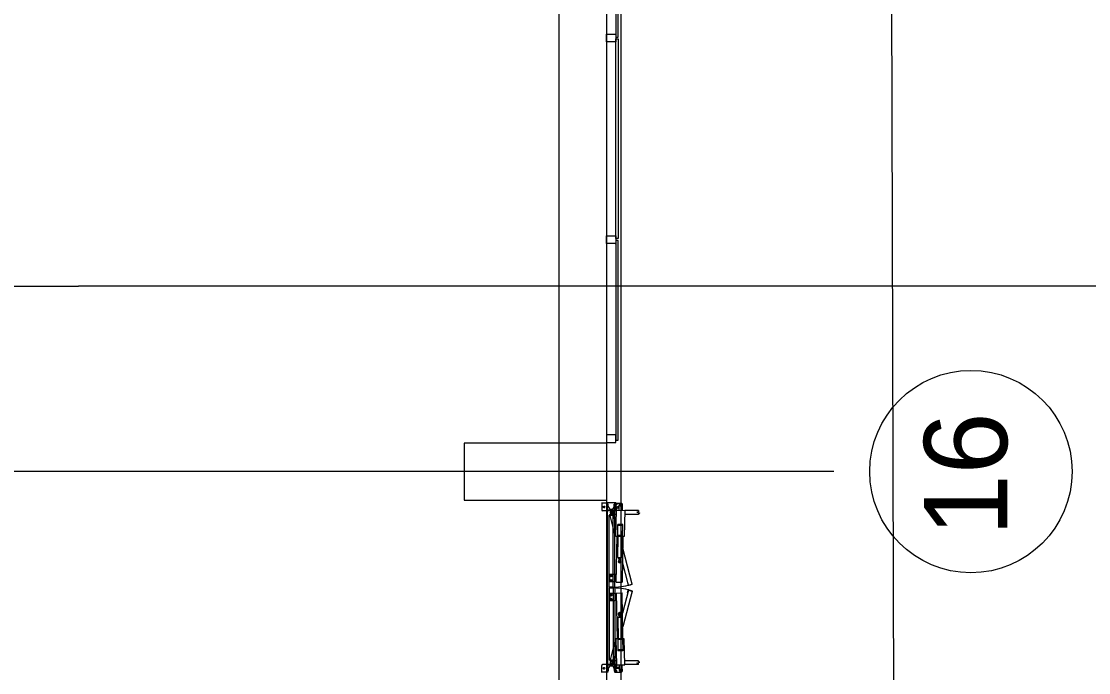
# Model space of a CAD drawing. Extents: x -264031 to -263588, y -1242281 to -1242059.
# Drawn here: x -263801.2 to -263789.97, y -1242184 to -1242177.15 of the extents above; entities that cross this region are included whole.
import ezdxf

# ---------------------------------------------------------------- set-up
doc = ezdxf.new("R2010")
doc.units = 0
for name, color, linetype in [('HESCON_OSI_STAVBY_KFA', 7, 'Continuous'), ('KFA_2D_SITUACIA_DSP', 7, 'Continuous'), ('KFA_JESTV_IS_DSP_-_KANAL_SPLASK', 7, 'Continuous')]:
    doc.layers.add(name, color=color, linetype=linetype)

msp = doc.modelspace()

# ---------------------------------------------------------------- linework, layer by layer
at = {"layer": 'HESCON_OSI_STAVBY_KFA'}
for p, q in [((-263795.543, -1242083.237), (-263795.543, -1242246.707)), ((-263792.653, -1242181.882), (-263909.343, -1242181.882)), ((-263792.653, -1242181.882), (-263792.653, -1242181.882))]:
    msp.add_line(p, q, dxfattribs=at)
msp.add_circle((-263791.21, -1242181.882), 1.064, dxfattribs=at)
at = {"layer": 'KFA_2D_SITUACIA_DSP'}
for p, q in [((-263795.043, -1242101.769), (-263795.043, -1242226.995)), ((-263794.943, -1242175.212), (-263794.943, -1242177.312)), ((-263794.918, -1242177.312), (-263794.918, -1242175.212)), ((-263795.043, -1242177.362), (-263795.043, -1242177.282)), ((-263795.043, -1242177.282), (-263794.943, -1242177.282)), ((-263794.943, -1242177.362), (-263795.043, -1242177.362)), ((-263794.943, -1242177.282), (-263794.943, -1242177.322)), ((-263794.943, -1242177.312), (-263794.918, -1242177.312)), ((-263794.943, -1242177.322), (-263794.943, -1242177.362)), ((-263794.943, -1242179.432), (-263794.943, -1242177.332)), ((-263794.943, -1242177.332), (-263794.918, -1242177.332)), ((-263794.918, -1242177.332), (-263794.918, -1242179.432)), ((-263795.043, -1242179.482), (-263795.043, -1242179.402)), ((-263795.043, -1242179.402), (-263794.943, -1242179.402)), ((-263794.943, -1242179.482), (-263795.043, -1242179.482)), ((-263794.943, -1242179.402), (-263794.943, -1242179.492)), ((-263794.918, -1242179.432), (-263794.943, -1242179.432)), ((-263794.918, -1242179.452), (-263794.943, -1242179.452)), ((-263794.943, -1242179.452), (-263794.943, -1242181.552)), ((-263794.943, -1242179.492), (-263794.943, -1242179.482)), ((-263794.918, -1242181.552), (-263794.918, -1242179.452)), ((-263801.593, -1242179.932), (-263800.593, -1242179.932)), ((-263788.893, -1242179.932), (-263800.593, -1242179.932)), ((-263794.943, -1242181.497), (-263795.043, -1242181.497)), ((-263795.043, -1242181.497), (-263795.043, -1242181.577)), ((-263794.943, -1242181.537), (-263794.943, -1242181.497)), ((-263795.038, -1242181.582), (-263796.538, -1242181.582)), ((-263796.538, -1242181.582), (-263796.538, -1242182.182)), ((-263795.043, -1242181.577), (-263794.943, -1242181.577)), ((-263795.038, -1242182.182), (-263795.038, -1242181.582)), ((-263794.943, -1242181.577), (-263794.943, -1242181.537)), ((-263794.943, -1242181.552), (-263794.918, -1242181.552)), ((-263796.538, -1242182.182), (-263795.038, -1242182.182)), ((-263795.093, -1242182.208), (-263795.093, -1242182.284)), ((-263795.033, -1242182.214), (-263795.093, -1242182.214)), ((-263795.033, -1242182.294), (-263795.083, -1242182.294)), ((-263795.055, -1242182.254), (-263795.081, -1242182.254)), ((-263795.068, -1242182.241), (-263795.068, -1242182.267)), ((-263795.043, -1242182.208), (-263794.943, -1242182.208)), ((-263795.033, -1242183.102), (-263795.033, -1242182.208)), ((-263795.025, -1242182.224), (-263795.033, -1242182.224)), ((-263794.953, -1242182.288), (-263795.033, -1242182.288)), ((-263794.953, -1242182.294), (-263795.033, -1242182.294)), ((-263795.025, -1242182.245), (-263795.025, -1242182.224)), ((-263795.005, -1242182.288), (-263794.98, -1242182.288)), ((-263795.005, -1242182.288), (-263795.005, -1242182.298)), ((-263795.005, -1242182.298), (-263794.98, -1242182.298)), ((-263794.994, -1242182.298), (-263795.001, -1242182.308)), ((-263794.992, -1242182.298), (-263794.994, -1242182.298)), ((-263794.985, -1242182.308), (-263794.992, -1242182.298)), ((-263794.98, -1242182.288), (-263794.98, -1242182.298)), ((-263794.977, -1242182.301), (-263794.977, -1242182.326)), ((-263794.967, -1242182.301), (-263794.977, -1242182.301)), ((-263794.967, -1242182.333), (-263794.967, -1242182.293)), ((-263794.937, -1242182.293), (-263794.967, -1242182.293)), ((-263794.967, -1242182.301), (-263794.967, -1242182.326)), ((-263794.96, -1242182.245), (-263794.96, -1242182.224)), ((-263794.953, -1242182.224), (-263794.96, -1242182.224)), ((-263794.953, -1242183.102), (-263794.953, -1242182.208)), ((-263794.953, -1242182.213), (-263794.943, -1242182.213)), ((-263794.953, -1242182.213), (-263794.953, -1242182.283)), ((-263794.953, -1242182.283), (-263794.943, -1242182.283)), ((-263794.937, -1242182.294), (-263794.953, -1242182.294)), ((-263794.933, -1242182.223), (-263794.947, -1242182.223)), ((-263794.933, -1242182.272), (-263794.947, -1242182.272)), ((-263794.943, -1242182.213), (-263794.893, -1242182.213)), ((-263794.943, -1242182.213), (-263794.943, -1242182.283)), ((-263794.943, -1242182.232), (-263794.943, -1242182.215)), ((-263794.941, -1242182.215), (-263794.943, -1242182.215)), ((-263794.941, -1242182.232), (-263794.943, -1242182.232)), ((-263794.943, -1242182.253), (-263794.908, -1242182.253)), ((-263794.943, -1242182.281), (-263794.943, -1242182.264)), ((-263794.941, -1242182.264), (-263794.943, -1242182.264)), ((-263794.941, -1242182.281), (-263794.943, -1242182.281)), ((-263794.943, -1242182.564), (-263794.937, -1242182.289)), ((-263794.941, -1242182.232), (-263794.941, -1242182.215)), ((-263794.941, -1242182.23), (-263794.941, -1242182.217)), ((-263794.941, -1242182.217), (-263794.935, -1242182.217)), ((-263794.941, -1242182.223), (-263794.936, -1242182.223)), ((-263794.935, -1242182.23), (-263794.941, -1242182.23)), ((-263794.941, -1242182.281), (-263794.941, -1242182.264)), ((-263794.941, -1242182.279), (-263794.941, -1242182.266)), ((-263794.941, -1242182.266), (-263794.935, -1242182.266)), ((-263794.941, -1242182.272), (-263794.936, -1242182.272)), ((-263794.935, -1242182.279), (-263794.941, -1242182.279)), ((-263794.937, -1242182.289), (-263794.85, -1242182.29)), ((-263794.935, -1242182.217), (-263794.935, -1242182.23)), ((-263794.935, -1242182.266), (-263794.935, -1242182.279)), ((-263794.908, -1242182.254), (-263794.927, -1242182.254)), ((-263794.918, -1242182.253), (-263794.918, -1242182.264)), ((-263794.909, -1242182.289), (-263794.908, -1242182.233)), ((-263794.877, -1242182.233), (-263794.908, -1242182.233)), ((-263794.899, -1242182.223), (-263794.905, -1242182.233)), ((-263794.905, -1242182.233), (-263794.899, -1242182.244)), ((-263794.887, -1242182.223), (-263794.899, -1242182.223)), ((-263794.899, -1242182.244), (-263794.887, -1242182.244)), ((-263794.893, -1242182.218), (-263794.893, -1242182.249)), ((-263794.881, -1242182.233), (-263794.887, -1242182.223)), ((-263794.887, -1242182.244), (-263794.881, -1242182.233)), ((-263794.878, -1242182.234), (-263794.879, -1242182.29)), ((-263794.85, -1242182.29), (-263794.856, -1242182.565)), ((-263794.707, -1242182.293), (-263794.85, -1242182.293)), ((-263794.707, -1242182.293), (-263794.707, -1242182.305)), ((-263795.013, -1242183.097), (-263795.013, -1242182.339)), ((-263794.973, -1242182.339), (-263795.013, -1242182.339)), ((-263795.005, -1242182.339), (-263795.005, -1242182.329)), ((-263795.005, -1242182.329), (-263794.98, -1242182.329)), ((-263795.005, -1242182.343), (-263794.967, -1242182.333)), ((-263795.005, -1242182.339), (-263794.98, -1242182.339)), ((-263794.953, -1242182.54), (-263795.005, -1242182.343)), ((-263795.001, -1242182.319), (-263794.994, -1242182.329)), ((-263794.977, -1242182.325), (-263795.001, -1242182.332)), ((-263794.998, -1242182.341), (-263795.001, -1242182.332)), ((-263794.99, -1242182.329), (-263794.999, -1242182.321)), ((-263794.994, -1242182.329), (-263794.992, -1242182.329)), ((-263794.992, -1242182.329), (-263794.985, -1242182.319)), ((-263794.988, -1242182.328), (-263794.99, -1242182.329)), ((-263794.983, -1242182.317), (-263794.988, -1242182.328)), ((-263794.987, -1242182.305), (-263794.977, -1242182.312)), ((-263794.977, -1242182.314), (-263794.987, -1242182.322)), ((-263794.98, -1242182.339), (-263794.98, -1242182.329)), ((-263794.977, -1242182.312), (-263794.977, -1242182.314)), ((-263794.974, -1242182.335), (-263794.977, -1242182.325)), ((-263794.967, -1242182.326), (-263794.977, -1242182.326)), ((-263794.973, -1242183.097), (-263794.973, -1242182.339)), ((-263794.938, -1242182.333), (-263794.967, -1242182.333)), ((-263794.953, -1242182.386), (-263794.967, -1242182.333)), ((-263794.707, -1242182.333), (-263794.851, -1242182.333)), ((-263794.707, -1242182.305), (-263794.722, -1242182.309)), ((-263794.722, -1242182.309), (-263794.692, -1242182.318)), ((-263794.692, -1242182.318), (-263794.707, -1242182.322)), ((-263794.707, -1242182.322), (-263794.707, -1242182.333)), ((-263794.924, -1242182.564), (-263794.922, -1242182.438)), ((-263794.872, -1242182.439), (-263794.922, -1242182.438)), ((-263794.872, -1242182.449), (-263794.922, -1242182.448)), ((-263794.874, -1242182.565), (-263794.872, -1242182.439)), ((-263794.856, -1242182.565), (-263794.943, -1242182.564)), ((-263794.939, -1242183.045), (-263794.93, -1242182.564)), ((-263794.874, -1242182.555), (-263794.924, -1242182.554)), ((-263794.924, -1242182.787), (-263794.919, -1242182.564)), ((-263794.884, -1242182.788), (-263794.879, -1242182.565)), ((-263794.869, -1242182.565), (-263794.878, -1242183.046)), ((-263794.772, -1242183.066), (-263794.871, -1242182.689)), ((-263794.884, -1242182.788), (-263794.924, -1242182.787)), ((-263794.909, -1242182.808), (-263794.917, -1242182.821)), ((-263794.914, -1242182.792), (-263794.914, -1242182.787)), ((-263794.894, -1242182.792), (-263794.914, -1242182.792)), ((-263794.912, -1242182.792), (-263794.914, -1242182.793)), ((-263794.914, -1242182.799), (-263794.914, -1242182.793)), ((-263794.913, -1242182.8), (-263794.914, -1242182.799)), ((-263794.896, -1242182.8), (-263794.913, -1242182.8)), ((-263794.895, -1242182.792), (-263794.912, -1242182.792)), ((-263794.909, -1242182.799), (-263794.909, -1242182.793)), ((-263794.909, -1242182.808), (-263794.909, -1242182.8)), ((-263794.909, -1242182.808), (-263794.899, -1242182.808)), ((-263794.899, -1242182.8), (-263794.899, -1242182.793)), ((-263794.899, -1242182.808), (-263794.899, -1242182.8)), ((-263794.899, -1242182.808), (-263794.892, -1242182.822)), ((-263794.896, -1242182.8), (-263794.894, -1242182.8)), ((-263794.895, -1242182.792), (-263794.894, -1242182.793)), ((-263794.894, -1242182.792), (-263794.894, -1242182.787)), ((-263794.894, -1242182.8), (-263794.894, -1242182.793)), ((-263794.811, -1242183.076), (-263794.874, -1242182.833)), ((-263795.007, -1242183.04), (-263795.007, -1242182.965)), ((-263794.953, -1242182.965), (-263795.007, -1242182.965)), ((-263795, -1242182.976), (-263794.993, -1242182.972)), ((-263795, -1242182.984), (-263795, -1242182.976)), ((-263794.993, -1242182.972), (-263794.986, -1242182.976)), ((-263794.986, -1242182.976), (-263794.986, -1242182.984)), ((-263794.947, -1242182.965), (-263794.953, -1242182.965)), ((-263794.947, -1242183.04), (-263794.947, -1242182.965)), ((-263795.015, -1242183.095), (-263795.015, -1242183.065)), ((-263795.013, -1242183.065), (-263795.015, -1242183.065)), ((-263794.953, -1242183.04), (-263795.007, -1242183.04)), ((-263794.993, -1242182.988), (-263795, -1242182.984)), ((-263795, -1242183.021), (-263794.993, -1242183.017)), ((-263795, -1242183.029), (-263795, -1242183.021)), ((-263794.993, -1242183.033), (-263795, -1242183.029)), ((-263794.986, -1242182.984), (-263794.993, -1242182.988)), ((-263794.993, -1242183.017), (-263794.986, -1242183.021)), ((-263794.986, -1242183.029), (-263794.993, -1242183.033)), ((-263794.986, -1242183.021), (-263794.986, -1242183.029)), ((-263794.971, -1242183.065), (-263794.973, -1242183.065)), ((-263794.97, -1242183.08), (-263794.973, -1242183.08)), ((-263794.971, -1242183.095), (-263794.971, -1242183.065)), ((-263794.947, -1242183.04), (-263794.953, -1242183.04)), ((-263794.939, -1242183.045), (-263794.878, -1242183.046)), ((-263794.819, -1242183.045), (-263794.821, -1242183.046)), ((-263794.821, -1242183.046), (-263794.814, -1242183.075)), ((-263794.811, -1242183.076), (-263794.772, -1242183.066)), ((-263794.809, -1242183.078), (-263794.774, -1242183.068)), ((-263794.779, -1242183.035), (-263794.781, -1242183.035)), ((-263794.771, -1242183.064), (-263794.779, -1242183.035)), ((-263795.033, -1242183.102), (-263795.033, -1242183.997)), ((-263795.015, -1242183.109), (-263795.015, -1242183.139)), ((-263795.013, -1242183.139), (-263795.015, -1242183.139)), ((-263794.973, -1242183.097), (-263795.013, -1242183.097)), ((-263795.013, -1242183.107), (-263795.013, -1242183.866)), ((-263794.973, -1242183.107), (-263795.013, -1242183.107)), ((-263794.975, -1242183.099), (-263795.011, -1242183.099)), ((-263794.975, -1242183.105), (-263795.011, -1242183.105)), ((-263795.007, -1242183.165), (-263795.007, -1242183.24)), ((-263794.953, -1242183.165), (-263795.007, -1242183.165)), ((-263794.993, -1242183.172), (-263795, -1242183.176)), ((-263795, -1242183.176), (-263795, -1242183.184)), ((-263795, -1242183.184), (-263794.993, -1242183.188)), ((-263794.986, -1242183.176), (-263794.993, -1242183.172)), ((-263794.993, -1242183.188), (-263794.986, -1242183.184)), ((-263794.986, -1242183.184), (-263794.986, -1242183.176)), ((-263794.976, -1242183.096), (-263794.967, -1242183.096)), ((-263794.976, -1242183.109), (-263794.967, -1242183.109)), ((-263794.973, -1242183.107), (-263794.973, -1242183.866)), ((-263794.97, -1242183.125), (-263794.973, -1242183.125)), ((-263794.971, -1242183.139), (-263794.973, -1242183.139)), ((-263794.971, -1242183.109), (-263794.971, -1242183.139)), ((-263794.953, -1242183.102), (-263794.953, -1242183.997)), ((-263794.947, -1242183.165), (-263794.953, -1242183.165)), ((-263794.947, -1242183.165), (-263794.947, -1242183.24)), ((-263794.939, -1242183.16), (-263794.878, -1242183.159)), ((-263794.939, -1242183.16), (-263794.93, -1242183.641)), ((-263794.869, -1242183.64), (-263794.878, -1242183.159)), ((-263794.811, -1242183.129), (-263794.874, -1242183.372)), ((-263794.772, -1242183.139), (-263794.871, -1242183.516)), ((-263794.821, -1242183.159), (-263794.814, -1242183.13)), ((-263794.819, -1242183.16), (-263794.821, -1242183.159)), ((-263794.811, -1242183.129), (-263794.772, -1242183.139)), ((-263794.809, -1242183.127), (-263794.774, -1242183.137)), ((-263794.779, -1242183.17), (-263794.781, -1242183.17)), ((-263794.771, -1242183.141), (-263794.779, -1242183.17)), ((-263794.953, -1242183.24), (-263795.007, -1242183.24)), ((-263794.993, -1242183.217), (-263795, -1242183.221)), ((-263795, -1242183.221), (-263795, -1242183.229)), ((-263795, -1242183.229), (-263794.993, -1242183.233)), ((-263794.986, -1242183.221), (-263794.993, -1242183.217)), ((-263794.993, -1242183.233), (-263794.986, -1242183.229)), ((-263794.986, -1242183.229), (-263794.986, -1242183.221)), ((-263794.947, -1242183.24), (-263794.953, -1242183.24)), ((-263794.884, -1242183.417), (-263794.924, -1242183.418)), ((-263794.924, -1242183.418), (-263794.919, -1242183.641)), ((-263794.909, -1242183.397), (-263794.917, -1242183.384)), ((-263794.913, -1242183.405), (-263794.914, -1242183.406)), ((-263794.914, -1242183.406), (-263794.914, -1242183.412)), ((-263794.912, -1242183.413), (-263794.914, -1242183.412)), ((-263794.914, -1242183.413), (-263794.914, -1242183.418)), ((-263794.894, -1242183.413), (-263794.914, -1242183.413)), ((-263794.896, -1242183.405), (-263794.913, -1242183.405)), ((-263794.895, -1242183.413), (-263794.912, -1242183.413)), ((-263794.909, -1242183.397), (-263794.899, -1242183.397)), ((-263794.909, -1242183.397), (-263794.909, -1242183.405)), ((-263794.909, -1242183.406), (-263794.909, -1242183.412)), ((-263794.899, -1242183.397), (-263794.892, -1242183.383)), ((-263794.899, -1242183.397), (-263794.899, -1242183.405)), ((-263794.899, -1242183.405), (-263794.899, -1242183.412)), ((-263794.896, -1242183.405), (-263794.894, -1242183.405)), ((-263794.895, -1242183.413), (-263794.894, -1242183.412)), ((-263794.894, -1242183.405), (-263794.894, -1242183.412)), ((-263794.894, -1242183.413), (-263794.894, -1242183.418)), ((-263794.884, -1242183.417), (-263794.879, -1242183.64)), ((-263794.856, -1242183.64), (-263794.943, -1242183.641)), ((-263794.943, -1242183.641), (-263794.937, -1242183.916)), ((-263794.924, -1242183.641), (-263794.922, -1242183.767)), ((-263794.874, -1242183.65), (-263794.924, -1242183.651)), ((-263794.874, -1242183.64), (-263794.872, -1242183.766)), ((-263794.85, -1242183.915), (-263794.856, -1242183.64)), ((-263794.953, -1242183.665), (-263795.005, -1242183.862)), ((-263794.872, -1242183.756), (-263794.922, -1242183.757)), ((-263794.973, -1242183.866), (-263795.013, -1242183.866)), ((-263795.005, -1242183.862), (-263794.967, -1242183.872)), ((-263795.005, -1242183.866), (-263795.005, -1242183.876)), ((-263795.005, -1242183.866), (-263794.98, -1242183.866)), ((-263794.998, -1242183.864), (-263795.001, -1242183.873)), ((-263794.977, -1242183.88), (-263795.001, -1242183.873)), ((-263794.98, -1242183.866), (-263794.98, -1242183.876)), ((-263794.974, -1242183.87), (-263794.977, -1242183.88)), ((-263794.953, -1242183.819), (-263794.967, -1242183.872)), ((-263794.967, -1242183.871), (-263794.967, -1242183.911)), ((-263794.938, -1242183.871), (-263794.967, -1242183.871)), ((-263794.872, -1242183.766), (-263794.922, -1242183.767)), ((-263794.707, -1242183.871), (-263794.851, -1242183.871)), ((-263794.707, -1242183.883), (-263794.707, -1242183.871)), ((-263795.093, -1242183.997), (-263795.093, -1242183.921)), ((-263795.033, -1242183.911), (-263795.083, -1242183.911)), ((-263795.055, -1242183.951), (-263795.081, -1242183.951)), ((-263795.068, -1242183.964), (-263795.068, -1242183.938)), ((-263794.953, -1242183.911), (-263795.033, -1242183.911)), ((-263794.953, -1242183.917), (-263795.033, -1242183.917)), ((-263795.025, -1242183.981), (-263795.033, -1242183.981)), ((-263795.025, -1242183.96), (-263795.025, -1242183.981)), ((-263795.005, -1242183.876), (-263794.98, -1242183.876)), ((-263795.005, -1242183.907), (-263794.98, -1242183.907)), ((-263795.005, -1242183.917), (-263795.005, -1242183.907)), ((-263795.005, -1242183.917), (-263794.98, -1242183.917)), ((-263795.001, -1242183.886), (-263794.994, -1242183.876)), ((-263794.994, -1242183.907), (-263795.001, -1242183.897)), ((-263794.99, -1242183.876), (-263794.999, -1242183.884)), ((-263794.994, -1242183.876), (-263794.992, -1242183.876)), ((-263794.992, -1242183.907), (-263794.994, -1242183.907)), ((-263794.992, -1242183.876), (-263794.985, -1242183.886)), ((-263794.985, -1242183.897), (-263794.992, -1242183.907)), ((-263794.988, -1242183.877), (-263794.99, -1242183.876)), ((-263794.983, -1242183.888), (-263794.988, -1242183.877)), ((-263794.977, -1242183.89), (-263794.987, -1242183.883)), ((-263794.987, -1242183.9), (-263794.977, -1242183.892)), ((-263794.98, -1242183.917), (-263794.98, -1242183.907)), ((-263794.977, -1242183.904), (-263794.977, -1242183.879)), ((-263794.967, -1242183.879), (-263794.977, -1242183.879)), ((-263794.977, -1242183.892), (-263794.977, -1242183.89)), ((-263794.967, -1242183.904), (-263794.977, -1242183.904)), ((-263794.967, -1242183.904), (-263794.967, -1242183.879)), ((-263794.937, -1242183.911), (-263794.967, -1242183.911)), ((-263794.96, -1242183.96), (-263794.96, -1242183.981)), ((-263794.953, -1242183.981), (-263794.96, -1242183.981)), ((-263794.937, -1242183.911), (-263794.953, -1242183.911)), ((-263794.953, -1242183.922), (-263794.943, -1242183.922)), ((-263794.953, -1242183.992), (-263794.953, -1242183.922)), ((-263794.933, -1242183.932), (-263794.947, -1242183.932)), ((-263794.933, -1242183.981), (-263794.947, -1242183.981)), ((-263794.943, -1242183.992), (-263794.943, -1242183.922)), ((-263794.943, -1242183.924), (-263794.943, -1242183.941)), ((-263794.941, -1242183.924), (-263794.943, -1242183.924)), ((-263794.941, -1242183.941), (-263794.943, -1242183.941)), ((-263794.943, -1242183.951), (-263794.908, -1242183.951)), ((-263794.943, -1242183.973), (-263794.943, -1242183.99)), ((-263794.941, -1242183.973), (-263794.943, -1242183.973)), ((-263794.941, -1242183.924), (-263794.941, -1242183.941)), ((-263794.941, -1242183.926), (-263794.941, -1242183.939)), ((-263794.935, -1242183.926), (-263794.941, -1242183.926)), ((-263794.941, -1242183.932), (-263794.936, -1242183.932)), ((-263794.941, -1242183.939), (-263794.935, -1242183.939)), ((-263794.941, -1242183.973), (-263794.941, -1242183.99)), ((-263794.941, -1242183.975), (-263794.941, -1242183.988)), ((-263794.935, -1242183.975), (-263794.941, -1242183.975)), ((-263794.941, -1242183.981), (-263794.936, -1242183.981)), ((-263794.937, -1242183.916), (-263794.85, -1242183.915)), ((-263794.935, -1242183.939), (-263794.935, -1242183.926)), ((-263794.935, -1242183.988), (-263794.935, -1242183.975)), ((-263794.908, -1242183.951), (-263794.927, -1242183.951)), ((-263794.918, -1242183.951), (-263794.918, -1242183.941)), ((-263794.909, -1242183.916), (-263794.908, -1242183.972)), ((-263794.877, -1242183.971), (-263794.908, -1242183.971)), ((-263794.905, -1242183.971), (-263794.899, -1242183.961)), ((-263794.899, -1242183.982), (-263794.905, -1242183.971)), ((-263794.899, -1242183.961), (-263794.887, -1242183.961)), ((-263794.887, -1242183.982), (-263794.899, -1242183.982)), ((-263794.893, -1242183.987), (-263794.893, -1242183.956)), ((-263794.887, -1242183.961), (-263794.881, -1242183.971)), ((-263794.881, -1242183.971), (-263794.887, -1242183.982)), ((-263794.878, -1242183.971), (-263794.879, -1242183.915)), ((-263794.707, -1242183.911), (-263794.85, -1242183.911)), ((-263794.722, -1242183.896), (-263794.692, -1242183.887)), ((-263794.707, -1242183.9), (-263794.722, -1242183.896)), ((-263794.692, -1242183.887), (-263794.707, -1242183.883)), ((-263794.707, -1242183.911), (-263794.707, -1242183.9)), ((-263795.033, -1242183.991), (-263795.093, -1242183.991)), ((-263794.953, -1242183.992), (-263794.943, -1242183.992)), ((-263794.941, -1242183.99), (-263794.943, -1242183.99)), ((-263794.943, -1242183.991), (-263794.893, -1242183.991)), ((-263794.941, -1242183.988), (-263794.935, -1242183.988))]:
    msp.add_line(p, q, dxfattribs=at)
msp.add_lwpolyline([(-263794.893, -1242227.382), (-263808.968, -1242241.457), (-263894.968, -1242241.457), (-263909.043, -1242227.382), (-263909.043, -1242196.333), (-263914.143, -1242196.333), (-263914.143, -1242132.433), (-263909.043, -1242132.433), (-263909.043, -1242101.382), (-263894.968, -1242087.307), (-263808.968, -1242087.307), (-263794.893, -1242101.382), (-263794.893, -1242227.382)], dxfattribs=at)
for centre, radius in [((-263795.068, -1242182.254), 0.008), ((-263794.893, -1242182.233), 0.0126), ((-263794.893, -1242182.233), 0.0102), ((-263794.905, -1242182.828), 0.00952), ((-263794.905, -1242182.828), 0.00645), ((-263794.905, -1242182.828), 0.005), ((-263794.993, -1242182.98), 0.0084), ((-263794.993, -1242182.98), 0.0068), ((-263794.993, -1242183.025), 0.0084), ((-263794.993, -1242183.025), 0.0068), ((-263794.993, -1242183.18), 0.0084), ((-263794.993, -1242183.18), 0.0068), ((-263794.993, -1242183.225), 0.0084), ((-263794.993, -1242183.225), 0.0068), ((-263794.905, -1242183.377), 0.00952), ((-263794.905, -1242183.377), 0.00645), ((-263794.905, -1242183.377), 0.005), ((-263795.068, -1242183.951), 0.008), ((-263794.893, -1242183.971), 0.0126), ((-263794.893, -1242183.971), 0.0102)]:
    msp.add_circle(centre, radius, dxfattribs=at)
for centre, radius, start, end in [((-263795.083, -1242182.284), 0.01, 180, 270), ((-263794.993, -1242182.245), 0.0325, 180, 0), ((-263794.993, -1242182.313), 0.01, 323.6139, 216.3861), ((-263794.993, -1242182.313), 0.01, 53.6139, 306.3861), ((-263794.993, -1242182.313), 0.01, 338.6139, 231.3861), ((-263794.942, -1242182.22), 0.0068, 330, 30), ((-263794.942, -1242182.227), 0.0068, 330, 30), ((-263794.942, -1242182.269), 0.0068, 330, 30), ((-263794.942, -1242182.276), 0.0068, 330, 30), ((-263794.918, -1242182.254), 0.008, 176.4167, 3.5833), ((-263794.893, -1242182.233), 0.015, 358.86, 178.86), ((-263794.893, -1242182.233), 0.02, 317.4504, 90), ((-263794.993, -1242182.313), 0.01, 143.6139, 36.3861), ((-263794.905, -1242182.828), 0.014, 150.1229, 27.5971), ((-263794.911, -1242182.796), 0.00432, 54.2666, 123.4534), ((-263794.911, -1242182.796), 0.00432, 234.2666, 303.4534), ((-263794.904, -1242182.808), 0.0161, 71.1601, 106.5599), ((-263794.904, -1242182.784), 0.0161, 251.1601, 286.5599), ((-263794.897, -1242182.797), 0.00432, 54.2666, 123.4534), ((-263794.899, -1242182.793), 0.0001, 178.86, 248.0468), ((-263794.899, -1242182.8), 0.0001, 109.6732, 178.86), ((-263794.897, -1242182.796), 0.00432, 234.2666, 303.4534), ((-263794.993, -1242182.313), 0.786, 270, 285), ((-263794.81, -1242183.074), 0.004, 195, 285), ((-263794.775, -1242183.065), 0.004, 285, 15), ((-263795.011, -1242183.095), 0.004, 180, 270), ((-263795.011, -1242183.109), 0.004, 90, 180), ((-263794.993, -1242183.891), 0.786, 75, 90), ((-263794.975, -1242183.095), 0.004, 270, 0), ((-263794.975, -1242183.109), 0.004, 0, 90), ((-263794.81, -1242183.131), 0.004, 75, 165), ((-263794.775, -1242183.14), 0.004, 345, 75), ((-263794.905, -1242183.377), 0.014, 332.4029, 209.8771), ((-263794.911, -1242183.409), 0.00432, 56.5466, 125.7334), ((-263794.911, -1242183.409), 0.00432, 236.5466, 305.7334), ((-263794.904, -1242183.421), 0.0161, 73.4401, 108.8399), ((-263794.904, -1242183.397), 0.0161, 253.4401, 288.8399), ((-263794.897, -1242183.409), 0.00432, 56.5466, 125.7334), ((-263794.899, -1242183.405), 0.0001, 181.14, 250.3268), ((-263794.897, -1242183.408), 0.00432, 236.5466, 305.7334), ((-263794.899, -1242183.412), 0.0001, 111.9532, 181.14), ((-263795.083, -1242183.921), 0.01, 90, 180), ((-263794.993, -1242183.96), 0.0325, 0, 180), ((-263794.993, -1242183.891), 0.01, 323.6139, 216.3861), ((-263794.993, -1242183.891), 0.01, 53.6139, 306.3861), ((-263794.993, -1242183.891), 0.01, 128.6139, 21.3861), ((-263794.993, -1242183.891), 0.01, 143.6139, 36.3861), ((-263794.942, -1242183.929), 0.0068, 330, 30), ((-263794.942, -1242183.936), 0.0068, 330, 30), ((-263794.942, -1242183.978), 0.0068, 330, 30), ((-263794.942, -1242183.985), 0.0068, 330, 30), ((-263794.918, -1242183.951), 0.008, 356.4167, 183.5833), ((-263794.893, -1242183.971), 0.015, 181.14, 1.14), ((-263794.893, -1242183.971), 0.02, 270, 42.5496)]:
    msp.add_arc(centre, radius, start, end, dxfattribs=at)
at = {"layer": 'KFA_JESTV_IS_DSP_-_KANAL_SPLASK'}
msp.add_line((-263792.059, -1242173.066), (-263791.925, -1242214.473), dxfattribs=at)

# ---------------------------------------------------------------- texts
at = {"layer": 'HESCON_OSI_STAVBY_KFA'}
msp.add_text('16', height=0.875, rotation=90, dxfattribs=at).set_placement((-263790.829, -1242182.562))

doc.saveas('drawing.dxf')
